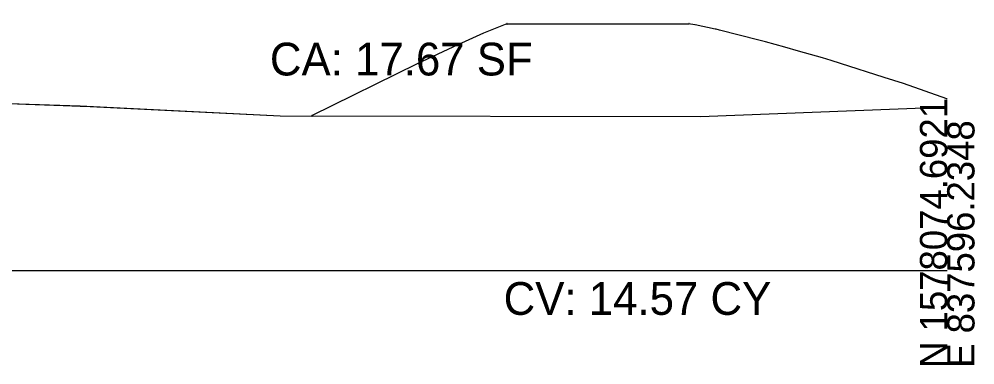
# Model space of a CAD drawing. Extents: x -26 to 303, y -16 to 6048.
# Drawn here: x 204.7 to 302.8, y 1490.3 to 1525.8 of the extents above; entities that cross this region are included whole.
import ezdxf

# ---------------------------------------------------------------- set-up
doc = ezdxf.new("R2010")
doc.units = 0
for name, color, linetype in [('DTM_P_FINISHED_GRADE', 7, 'Continuous'), ('DTM_TEMP_DROP', 7, 'Continuous'), ('DTM_X_FLOW_ARROWS', 7, 'Continuous'), ('DTM_X_GROUND', 7, 'Continuous'), ('XS_CELL', 7, 'Continuous'), ('XS_P_GROUND', 7, 'Continuous'), ('XS_SHEET_EW_TX_AREA', 7, 'Continuous'), ('XS_SHEET_EW_TX_VOLUME', 7, 'Continuous')]:
    doc.layers.add(name, color=color, linetype=linetype)

msp = doc.modelspace()

# ---------------------------------------------------------------- linework, layer by layer
at = {"layer": 'DTM_P_FINISHED_GRADE'}
msp.add_lwpolyline([(254.804, 1525.3), (254.982, 1525.3), (256.273, 1525.3), (256.542, 1525.3), (256.682, 1525.3), (259.397, 1525.3), (260.709, 1525.3), (263.717, 1525.3), (264.183, 1525.3), (267.094, 1525.3), (267.371, 1525.3), (270.506, 1525.3), (270.657, 1525.3), (273.459, 1525.3)], dxfattribs=at)
at = {"layer": 'DTM_X_GROUND'}
for points in [[(99.025, 1515.516), (113.066, 1516.674), (117.493, 1517.266), (133.178, 1523.176), (138.871, 1525.305), (142.418, 1525.452), (149.919, 1525.735), (158.682, 1525.77), (161.672, 1525.781), (163.69, 1525.637), (166.232, 1525.445), (169.417, 1523.693), (180.467, 1517.835), (187.086, 1517.627), (203.677, 1517.108), (211.013, 1516.878), (231.548, 1515.875), (274.675, 1515.807), (298.485, 1516.717), (300, 1516.718)], [(203.677, 1517.108), (205.443, 1517.052), (209.278, 1516.932), (211.013, 1516.866), (212.04, 1516.828), (231.548, 1515.875), (274.675, 1515.807), (298.485, 1516.717), (300, 1516.718)]]:
    msp.add_lwpolyline(points, dxfattribs=at)
at = {"layer": 'XS_CELL'}
msp.add_line((150, 1500), (300, 1500), dxfattribs=at)
at = {"layer": 'XS_P_GROUND'}
for points in [[(254.804, 1525.3), (252.405, 1524.335), (249.788, 1523.133), (245.6, 1521.211), (234.77, 1515.87)], [(300, 1517.586), (299.952, 1517.603), (295.502, 1519.16), (293.535, 1519.797), (289.058, 1521.245), (288.101, 1521.533), (287.19, 1521.807), (284.753, 1522.507), (283.344, 1522.911), (281.336, 1523.452), (280.672, 1523.631), (276.617, 1524.656), (276.279, 1524.741), (276.171, 1524.766), (274.143, 1525.181), (274.106, 1525.188), (273.459, 1525.3)]]:
    msp.add_lwpolyline(points, dxfattribs=at)

# ---------------------------------------------------------------- texts
at = {"layer": 'DTM_TEMP_DROP'}
for p in [(254.725, 1525.18), (273.381, 1525.18)]:
    msp.add_text('X', height=0.24, dxfattribs=at).set_placement(p)
at = {"layer": 'DTM_X_FLOW_ARROWS'}
msp.add_text('X', height=0.24, dxfattribs=at).set_placement((234.691, 1515.75))
at = {"layer": 'XS_CELL'}
for s, p in [('N 1578074.6921', (300, 1490)), ('E 837596.2348', (302.8, 1490))]:
    msp.add_text(s, height=2.8, rotation=90, dxfattribs=at).set_placement(p)
at = {"layer": 'XS_SHEET_EW_TX_AREA'}
msp.add_text('CA: 17.67 SF', height=3.36, dxfattribs=at).set_placement((230.487, 1520))
at = {"layer": 'XS_SHEET_EW_TX_VOLUME'}
msp.add_text('CV: 14.57 CY', height=3.36, dxfattribs=at).set_placement((254.474, 1495.44))

doc.saveas('drawing.dxf')
